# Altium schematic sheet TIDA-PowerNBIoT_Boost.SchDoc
size 431 x 279 mm; Date: Not shown in title block; ApprovedBy: Not shown in title block; CheckedBy: Not shown in title block; Author: Not shown in title block; CompanyName: Not shown in title block; Engineer: Not shown in title block; Organization: Not shown in title block; Address1: Not shown in title block; Address2: Not shown in title block; Address3: Not shown in title block; Address4: Not shown in title block; DocumentNumber: 1; Revision: Use project parameter SCH_Rev; SheetNumber: 2; SheetTotal: 3; PageSetup: Record=PageOptions¦CenterHorizontal=True¦CenterVertical=True¦PrintScale=1.00¦XCorrection=1.00¦YCorrection=1.00¦PrintKind=0¦BorderSize=5000000¦LeftOffset=0¦BottomOffset=0¦Orientation=2¦PaperLength=1000¦PaperWidth=1000¦Scale=100¦PaperSource=15¦PrintQuality=600¦MediaType=1¦DitherType=10¦PaperKind=Letter¦PrintScaleMode=1
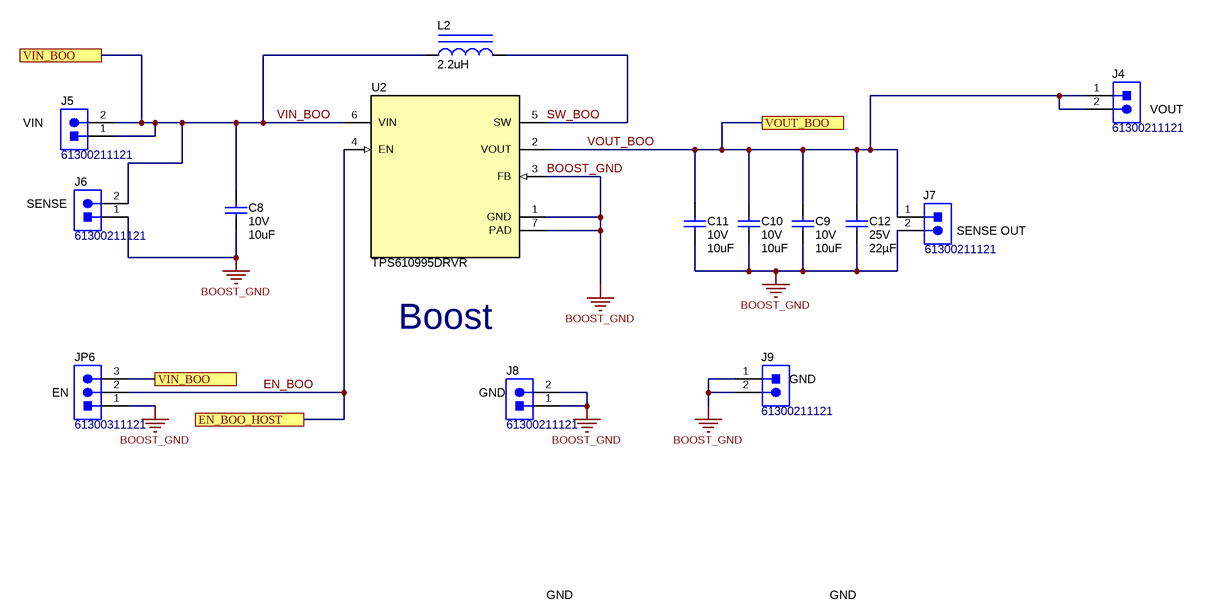
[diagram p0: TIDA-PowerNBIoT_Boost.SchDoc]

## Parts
C8  VDC_V: 10V  ValueDisplayed: 10uF  [0603]  (hidden comment: GRM188Z71A106MA73D)
C9  VDC_V: 10V  ValueDisplayed: 10uF  [0603]  (hidden comment: GRM188Z71A106MA73D)
C10  VDC_V: 10V  ValueDisplayed: 10uF  [0603]  (hidden comment: GRM188Z71A106MA73D)
C11  VDC_V: 10V  ValueDisplayed: 10uF  [0603]  (hidden comment: GRM188Z71A106MA73D)
C12  VDC_V: 25V  ValueDisplayed: 22µF  [0805_HV]  (hidden comment: TMK212B7225KG-TR)
J4  61300211121  [WURTH_61300211121]
J5  61300211121  [WURTH_61300211121]
J6  61300211121  [WURTH_61300211121]
J7  61300211121  [WURTH_61300211121]
J8  61300211121  [WURTH_61300211121]
J9  61300211121  [WURTH_61300211121]
JP6  61300311121  [WURTH_61300311121]
L2  ValueDisplayed: 2.2uH  [WE_LQS_252012]  (hidden comment: 74404024022)
U2  TPS610995DRVR  [DRV0006A]

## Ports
EN_BOO_HOST, VIN_BOO, VOUT_BOO

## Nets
BOOST_GND: C8.2 C9.2 C10.2 C11.2 C12.2 J6.1 J7.2 J8.1 J8.2 J9.1 J9.2 JP6.1 U2.1(GND) U2.3(FB) U2.7(PAD)
EN_BOO: JP6.2 U2.4(EN) ; port EN_BOO_HOST
SW_BOO: L2.2 U2.5(SW)
VIN_BOO: C8.1 J5.1 J5.2 J6.2 JP6.3 L2.1 U2.6(VIN) ; port VIN_BOO
VOUT_BOO: C9.1 C10.1 C11.1 C12.1 J4.1 J4.2 J7.1 U2.2(VOUT) ; port VOUT_BOO

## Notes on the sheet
- (near J5) VIN
- (near J4) VOUT
- (near J6) SENSE
- (near J7) SENSE OUT
- (near JP6) EN
- Boost
- (near J8) GND
- (near J9) GND
- GND

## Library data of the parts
C8-C11 = CMP-0007497-5: CAP, CERM, 10 uF, 10 V, +/- 20%, X7R, 0603; Manufacturer: MuRata; TaMin_C: -55°C; Polarized: N; SizeAreaWB_mm2: 4.68; Value1: Unknown; U/M: EA; Value: 10uF; TaMax_C: 125°C; SizeZ_mm: 1; SizeX_mm: 1.6; SizeY_mm: 0.8; SizeArea_mm2: 1.28; CompType: Capacitor; Cap_F: 10µF; AEC Category: Q200
C12 = CMP-0080705-1: CAP, CERM, 22 µF, 25 V,+/- 10%, X7R, 0805; Manufacturer: Taiyo Yuden; SizeAreaWB_mm2: 6.75; SizeArea_mm2: 2.5; AEC Qualified: N; AEC Category: Q200; Value: 22uF; TaMax_C: 125°C; SizeZ_mm: 1.45; TaMin_C: -55°C; SizeY_mm: 1.25; U/M: EA; CompType: Capacitor; SizeX_mm: 2; Cap_Case: 0805
J4-J9 = CMP-0054794-2: Header, 2.54 mm, 2x1, Gold, TH; Manufacturer: Wurth Elektronik; Shrouded: N; Gender: Male; Green_REACh: Passed; Pitch_mm: 2.54; Green_Lifecycle: Active; Row_Count: 1; Cert_UL: Y
JP6 = CMP-0054796-2: Header, 2.54 mm, 3x1, Gold, TH; Manufacturer: Wurth Elektronik; Pitch_mm: 2.54; Green_Lifecycle: Active; Cert_UL: Y; Shrouded: N; Green_REACh: Passed; Gender: Male; Row_Count: 1
L2 = CMP-0063791-1: Inductor, Wirewound, Ferrite, 2.2 uH, 1.8 A, 0.08 ohm, SMD; Manufacturer: Wurth Elektronik; Isat: 1.95A @ 30% inductance drop; Irms: 1.8A @ 40C rise; Green_Lifecycle: Active; SizeAreaWB_mm2: 10.5; DCR_ohm: 0.08; Green_REACh: Passed; Value: 2.2uH; Imax_A: 1.8A; SizeZ_mm: 1.2; SizeX_mm: 2.5; SizeY_mm: 2; SizeArea_mm2: 5; Ind_H: 2.2µH; AEC Qualified: N; AEC Category: Q200
U2 = CMP-0079929-1: Synchronous Boost Converter with 800 nA Ultra-Low Quiescent Current, DRV0006A (WSON-6); Alternate PartNumber: TPS610995DRVT; Alternate Manufacturer: Texas Instruments; SizeAreaWB_mm2: 9; SizeZ_mm: 0.8; SizeX_mm: 2; SizeArea_mm2: 4; CompType: IC; AEC Qualified: N; AEC Category: Q200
